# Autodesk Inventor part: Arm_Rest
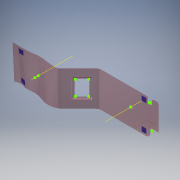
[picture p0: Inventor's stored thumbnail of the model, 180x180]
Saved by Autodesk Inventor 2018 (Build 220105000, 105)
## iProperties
Created: 2007-02
Part Number: Arm_Rest
Document SubType Name: Modeling
Designer: Autodesk, Inc.
Density: 1 g/cm^3
Material: Generic
Appearance: Default
Translation Standard: IGES 5.3
File Name: C:\My Documents\Customer Data\Arm_Rest.igs
Preprocessor: Some Cad System (Microsoft Windows NT Version 5.1 (x86)
Postprocessor: Build: 228, Release: 2008 - Date: Tue 02/06/2007
Sent Units: MM
Uncertainty: 3.1505e-06
Author: Autodesk, Inc.
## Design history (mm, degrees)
feature "Arm Rest"
feature "Nets"
sketch "3D Arm Rest"
sketch "3D Chg_B"
node "X 2400"
pattern_linear "Rectangular Pattern1" dims "d3" = 100
node "Z 2500"
pattern_linear "Rectangular Pattern2" dims "d7" = 100
workaxis "Work Axis2"
  workaxis "Work Axis1"
sketch "Sketch2"
  geometry: C1 r 17.117 at (0, 0)
  constraints: 1 centre point
sketch "Sketch3"
  geometry: L1 (-2839.194, 2558.75)-(-2990.484, 2558.75) reference; L2 (-3009.516, 2558.75)-(-3150, 2558.75) reference; L3 (-3150, 2560)-(-3009.516, 2560) reference; L4 (-2990.484, 2560)-(-2839.194, 2560) reference; L5 (-3009.5, 2560)-(-3009.5, 2558.75) reference; L6 (-2990.5, 2558.75)-(-2990.5, 2560) reference; L7 (-2593.5, 2663.217)-(-2593.5, 2664.455) reference; L8 (-2606.5, 2665.653)-(-2606.5, 2664.401) reference; L9 (-3150, 2558.75)-(-3150, 2560) reference; L10 (-2795.328, 2582.46)-(-2794.444, 2581.576) reference; L11 (-2754.704, 2621.315)-(-2755.588, 2622.199) reference; L12 (-2801.727, 2574.562)-(-2808.385, 2576.346) reference; L13 (-2747.789, 2628.231)-(-2754.704, 2621.315) reference; L14 (-2794.444, 2581.576)-(-2801.359, 2574.661) reference; L15 (-2726.005, 2658.995)-(-2749.375, 2635.625) reference; L16 (-2808.753, 2576.247)-(-2817.097, 2567.903) reference; L17 (-2809.481, 2577.287)-(-2802.399, 2575.389) reference; L18 (-2748.517, 2629.27)-(-2750.415, 2636.353) reference; L19 (-2802.399, 2575.389)-(-2795.328, 2582.46) reference; L20 (-2755.588, 2622.199)-(-2748.517, 2629.27) reference; L21 (-2749.474, 2635.257)-(-2747.69, 2628.599) reference; L22 (-2466.496, 2667.323)-(-2466.566, 2666.072) reference; L23 (-2817.981, 2568.787)-(-2809.481, 2577.287) reference; L24 (-2750.415, 2636.353)-(-2726.889, 2659.879) reference; C1 r 28.379 at (0, 0); A1 r 0.381 centre (-2801.629, 2574.93) between (-2801.727, 2574.562) and (-2801.359, 2574.661) reference; A2 r 0.381 centre (-2748.058, 2628.5) between (-2747.789, 2628.231) and (-2747.69, 2628.599) reference; A3 r 0.381 centre (-2808.483, 2575.978) between (-2808.385, 2576.346) and (-2808.753, 2576.247) reference; A4 r 0.381 centre (-2749.106, 2635.355) between (-2749.375, 2635.625) and (-2749.474, 2635.257) reference; A5 r 31.25 centre (-2839.194, 2590) between (-2839.194, 2558.75) and (-2817.097, 2567.903) reference; 11 further points
  constraints: 1 centre point, 7 other
  node "Project Cut Edges3"
sketch "Sketch7"
  geometry: C1 r 16.625 at (0, 0); 1 further point
  constraints: 1 centre point
node "X 2500"
node "X 2600"
node "X 2700"
node "X 2800"
node "X 2900"
node "X 3000"
node "X 3100"
node "X 3200"
node "z 2600"
node "Z 2700"
body "Srf1"
body "Srf2"
